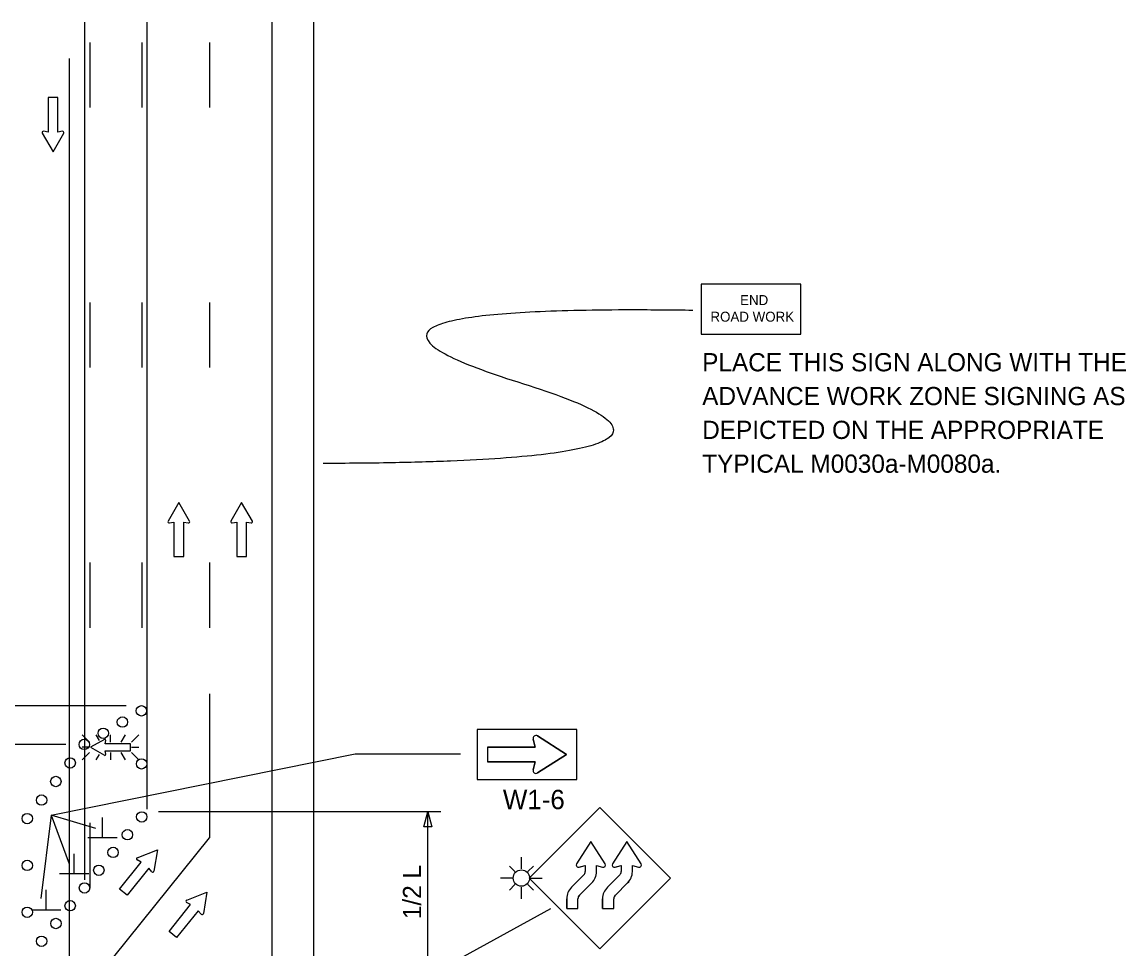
# Model space of a CAD drawing. Extents: x 16525 to 18479, y 5726 to 6926.
# Drawn here: x 16973 to 17397.4, y 6569.7 to 6926.1 of the extents above; entities that cross this region are included whole.
import ezdxf

# ---------------------------------------------------------------- set-up
doc = ezdxf.new("R2010")
doc.units = 0
for name, color, linetype in [('ALI_LEGAL_EX', 7, 'Continuous'), ('MT_SCRATCH_LEVEL_E', 7, 'Continuous'), ('PAVT_EDGE_EX', 7, 'Continuous'), ('TRAFFIC_SIGNS_PR', 7, 'Continuous'), ('TYPICAL_TEXT_DIMEN_PR', 7, 'Continuous')]:
    doc.layers.add(name, color=color, linetype=linetype)

msp = doc.modelspace()

# ---------------------------------------------------------------- linework, layer by layer
at = {"layer": 'ALI_LEGAL_EX'}
for points in [[(16999, 6918.24), (16999, 6893.24)], [(17019, 6918.24), (17019, 6893.24)], [(17045, 6918.24), (17045, 6893.24)], [(16999, 6818.24), (16999, 6793.24)], [(16999, 6818.24), (16999, 6793.24)], [(17019, 6818.24), (17019, 6793.24)], [(17019, 6818.24), (17019, 6793.24)], [(17045, 6818.24), (17045, 6793.24)], [(17045, 6818.24), (17045, 6793.24)], [(16999, 6718.24), (16999, 6693.24)], [(16999, 6718.24), (16999, 6693.24)], [(17019, 6718.24), (17019, 6693.24)], [(17019, 6718.24), (17019, 6693.24)], [(17045, 6718.24), (17045, 6693.24)], [(17045, 6718.24), (17045, 6693.24)], [(16999, 6618.24), (16999, 6593.24)], [(16999, 6618.24), (16999, 6593.24)]]:
    msp.add_lwpolyline(points, dxfattribs=at)
at = {"layer": 'MT_SCRATCH_LEVEL_E'}
for p, q in [((16986.74, 6897.03), (16983, 6897.03)), ((16983, 6897.03), (16983, 6883.77)), ((16986.74, 6897.03), (16983, 6897.03)), ((16983, 6897.03), (16983, 6883.77)), ((16986.74, 6883.77), (16986.74, 6897.03)), ((16986.74, 6883.77), (16986.74, 6897.03)), ((16980.74, 6883.4), (16984.89, 6876.16)), ((16980.74, 6883.4), (16984.89, 6876.16)), ((16983, 6883.77), (16981.22, 6884.09)), ((16983, 6883.77), (16981.22, 6884.09)), ((16984.89, 6876.16), (16989, 6883.4)), ((16984.89, 6876.16), (16989, 6883.4)), ((16988.52, 6884.09), (16986.74, 6883.77)), ((16988.52, 6884.09), (16986.74, 6883.77)), ((17033.24, 6741.41), (17029.13, 6734.17)), ((17033.24, 6741.41), (17029.13, 6734.17)), ((17037.39, 6734.17), (17033.24, 6741.41)), ((17037.39, 6734.17), (17033.24, 6741.41)), ((17057.41, 6741.41), (17053.3, 6734.17)), ((17057.41, 6741.41), (17053.3, 6734.17)), ((17061.56, 6734.17), (17057.41, 6741.41)), ((17061.56, 6734.17), (17057.41, 6741.41)), ((17029.61, 6733.49), (17031.39, 6733.8)), ((17029.61, 6733.49), (17031.39, 6733.8)), ((17031.39, 6733.8), (17031.39, 6720.55)), ((17031.39, 6733.8), (17031.39, 6720.55)), ((17035.13, 6720.55), (17035.13, 6733.8)), ((17035.13, 6733.8), (17036.91, 6733.49)), ((17035.13, 6720.55), (17035.13, 6733.8)), ((17035.13, 6733.8), (17036.91, 6733.49)), ((17053.78, 6733.49), (17055.56, 6733.8)), ((17053.78, 6733.49), (17055.56, 6733.8)), ((17055.56, 6733.8), (17055.56, 6720.55)), ((17055.56, 6733.8), (17055.56, 6720.55)), ((17059.3, 6720.55), (17059.3, 6733.8)), ((17059.3, 6733.8), (17061.08, 6733.49)), ((17059.3, 6720.55), (17059.3, 6733.8)), ((17059.3, 6733.8), (17061.08, 6733.49)), ((17031.39, 6720.55), (17035.13, 6720.55)), ((17031.39, 6720.55), (17035.13, 6720.55)), ((17055.56, 6720.55), (17059.3, 6720.55)), ((17055.56, 6720.55), (17059.3, 6720.55)), ((17017.25, 6604.77), (17025.02, 6607.81)), ((17017.25, 6604.77), (17025.02, 6607.81)), ((17025.02, 6607.81), (17023.68, 6599.59)), ((17025.02, 6607.81), (17023.68, 6599.59)), ((17010.46, 6592.74), (17018.78, 6603.07)), ((17010.46, 6592.74), (17018.78, 6603.07)), ((17021.69, 6600.72), (17013.38, 6590.4)), ((17021.69, 6600.72), (17013.38, 6590.4)), ((17018.78, 6603.07), (17017.19, 6603.94)), ((17018.78, 6603.07), (17017.19, 6603.94)), ((17022.88, 6599.36), (17021.69, 6600.72)), ((17022.88, 6599.36), (17021.69, 6600.72)), ((17013.38, 6590.4), (17010.46, 6592.74)), ((17013.38, 6590.4), (17010.46, 6592.74)), ((17036.29, 6588.46), (17044.06, 6591.49)), ((17036.29, 6588.46), (17044.06, 6591.49)), ((17044.06, 6591.49), (17042.72, 6583.28)), ((17044.06, 6591.49), (17042.72, 6583.28)), ((17037.81, 6586.75), (17036.23, 6587.62)), ((17037.81, 6586.75), (17036.23, 6587.62)), ((17029.5, 6576.43), (17037.81, 6586.75)), ((17029.5, 6576.43), (17037.81, 6586.75)), ((17040.73, 6584.41), (17032.41, 6574.08)), ((17040.73, 6584.41), (17032.41, 6574.08)), ((17041.92, 6583.05), (17040.73, 6584.41)), ((17041.92, 6583.05), (17040.73, 6584.41)), ((17032.41, 6574.08), (17029.5, 6576.43)), ((17032.41, 6574.08), (17029.5, 6576.43))]:
    msp.add_line(p, q, dxfattribs=at)
for centre, start, end in [((16981.15, 6883.63), 80.0362, 209.7731), ((16981.15, 6883.63), 80.0362, 209.7731), ((16988.59, 6883.63), 330.4248, 99.9638), ((16988.59, 6883.63), 330.4248, 99.9638), ((17029.54, 6733.95), 150.4248, 279.9638), ((17029.54, 6733.95), 150.4248, 279.9638), ((17036.98, 6733.95), 260.0362, 29.7731), ((17036.98, 6733.95), 260.0362, 29.7731), ((17053.71, 6733.95), 150.4248, 279.9638), ((17053.71, 6733.95), 150.4248, 279.9638), ((17061.15, 6733.95), 260.0362, 29.7731), ((17061.15, 6733.95), 260.0362, 29.7731), ((17017.43, 6604.34), 111.3861, 241.123), ((17017.43, 6604.34), 111.3861, 241.123), ((17023.22, 6599.67), 221.1954, 350.7344), ((17023.22, 6599.67), 221.1954, 350.7344), ((17036.47, 6588.02), 111.3861, 241.123), ((17036.47, 6588.02), 111.3861, 241.123), ((17042.26, 6583.36), 221.1954, 350.7344), ((17042.26, 6583.36), 221.1954, 350.7344)]:
    msp.add_arc(centre, 0.463, start, end, dxfattribs=at)
at = {"layer": 'PAVT_EDGE_EX'}
for p, q in [((16997, 6926.09), (16997, 6596.31)), ((17021, 6926.09), (17021, 6623.4)), ((17069, 6926.09), (17069, 6062.8)), ((17085, 6926.09), (17085, 6062.8)), ((16991.07, 6912.1), (16991.07, 6082.91)), ((16997, 6871.73), (16997, 6598.71)), ((17021, 6871.73), (17021, 6629.58)), ((17045, 6667.86), (17045, 6612.39)), ((16997, 6552.78), (17045, 6612.39))]:
    msp.add_line(p, q, dxfattribs=at)
at = {"layer": 'TRAFFIC_SIGNS_PR'}
for p, q in [((16996.08, 6652.08), (16998.9, 6649.26)), ((17002.8, 6649.89), (17001.54, 6652.08)), ((17006.99, 6649.26), (17006.99, 6652.08)), ((17011.12, 6649.26), (17012.75, 6652.08)), ((17015.07, 6649.26), (17017.89, 6652.08)), ((17171.18, 6651.59), (17182.34, 6644.49)), ((16998.9, 6647.23), (16996.08, 6647.23)), ((17015.07, 6647.23), (17017.89, 6647.23)), ((17151.94, 6647.29), (17170.34, 6647.29)), ((17151.94, 6647.29), (17151.94, 6641.69)), ((17170.34, 6647.29), (17169.5, 6650.35)), ((16996.08, 6642.38), (16998.9, 6645.19)), ((17001.52, 6642.37), (17002.72, 6644.47)), ((17006.99, 6645.19), (17006.99, 6642.37)), ((17012.77, 6642.37), (17011.15, 6645.19)), ((17015.07, 6645.19), (17017.89, 6642.37)), ((17182.34, 6644.49), (17171.18, 6637.39)), ((17170.34, 6641.69), (17151.94, 6641.69)), ((17169.5, 6638.63), (17170.34, 6641.69)), ((17195.14, 6624.05), (17167.99, 6596.9)), ((17222.29, 6596.9), (17195.14, 6624.05)), ((17164.98, 6600.52), (17164.98, 6605.03)), ((17162.46, 6599.48), (17160.36, 6601.59)), ((17167.49, 6599.48), (17169.6, 6601.59)), ((17161.82, 6596.97), (17156.99, 6596.97)), ((17167.99, 6596.9), (17195.14, 6569.75)), ((17168.13, 6596.97), (17173.01, 6596.97)), ((17184.27, 6593.44), (17188.99, 6598.15)), ((17188.99, 6598.15), (17184.27, 6593.44)), ((17195.14, 6569.75), (17222.29, 6596.9)), ((17198.07, 6593.44), (17202.78, 6598.15)), ((17202.78, 6598.15), (17198.07, 6593.44)), ((17162.46, 6594.46), (17160.36, 6592.35)), ((17164.98, 6589), (17164.98, 6593.41)), ((17167.49, 6594.46), (17169.6, 6592.35)), ((17187.32, 6590.38), (17192.04, 6595.1)), ((17187.32, 6590.38), (17192.04, 6595.1)), ((17201.12, 6590.38), (17205.83, 6595.1)), ((17201.12, 6590.38), (17205.83, 6595.1)), ((17182.4, 6585.32), (17182.4, 6589.02)), ((17186.72, 6585.32), (17186.72, 6589.02)), ((17196.2, 6585.32), (17196.2, 6589.02)), ((17200.52, 6585.32), (17200.52, 6589.02)), ((17182.4, 6585.32), (17186.72, 6585.32)), ((17196.2, 6585.32), (17200.52, 6585.32))]:
    msp.add_line(p, q, dxfattribs=at)
for points in [[(17234.07, 6806.15), (17272.47, 6806.15), (17272.47, 6825.35), (17234.07, 6825.35)], [(17147.94, 6634.89), (17186.34, 6634.89), (17186.34, 6654.09), (17147.94, 6654.09)]]:
    msp.add_lwpolyline(points, close=True, dxfattribs=at)
for points in [[(17171.18, 6637.39), (17182.34, 6644.49), (17171.18, 6651.59)], [(17004.66, 6650.24), (16999.35, 6647.23), (17004.66, 6644.19)], [(17005.16, 6644.54), (17004.93, 6645.84), (17014.65, 6645.84), (17014.65, 6648.58), (17004.93, 6648.58), (17005.16, 6649.89)], [(17169.5, 6650.35), (17170.34, 6647.29), (17151.94, 6647.29), (17151.94, 6641.69), (17170.34, 6641.69), (17169.5, 6638.63)], [(17197.19, 6602.43), (17191.71, 6611.04), (17186.23, 6602.42)], [(17197.19, 6602.42), (17191.71, 6611.04), (17186.23, 6602.42)], [(17210.99, 6602.43), (17205.5, 6611.04), (17200.02, 6602.42)], [(17210.99, 6602.42), (17205.5, 6611.04), (17200.02, 6602.42)], [(17187.19, 6601.13), (17189.55, 6601.78), (17189.55, 6599.48)], [(17187.19, 6601.13), (17188.02, 6601.36), (17189.55, 6601.78), (17189.55, 6599.48)], [(17193.86, 6599.41), (17193.87, 6601.78), (17196.23, 6601.13)], [(17193.86, 6599.41), (17193.87, 6601.78), (17196.23, 6601.13)], [(17200.98, 6601.13), (17203.34, 6601.78), (17203.34, 6599.48)], [(17200.98, 6601.13), (17201.82, 6601.36), (17203.34, 6601.78), (17203.34, 6599.48)], [(17207.66, 6599.41), (17207.66, 6601.78), (17210.03, 6601.13)], [(17207.66, 6599.41), (17207.66, 6601.78), (17210.03, 6601.13)], [(17182.4, 6589.02), (17182.4, 6585.32), (17186.72, 6585.32), (17186.72, 6589.02)], [(17196.2, 6589.02), (17196.2, 6585.32), (17200.52, 6585.32), (17200.52, 6589.02)]]:
    msp.add_lwpolyline(points, dxfattribs=at)
for centre, radius in [((17018.88, 6661.27), 2), ((17011.56, 6656.96), 2), ((17004.23, 6652.65), 2), ((16996.9, 6648.34), 2), ((16991.48, 6641.21), 2), ((17018.94, 6640.87), 2), ((16985.99, 6634.08), 2), ((16980.49, 6626.95), 2), ((16975, 6619.82), 2), ((17019, 6620.47), 2), ((17013.5, 6613.64), 2), ((17008, 6606.81), 2), ((16975, 6601.82), 2), ((17002.5, 6599.98), 2), ((17164.98, 6596.97), 3.15), ((16997, 6593.15), 2), ((16991.5, 6586.32), 2), ((16975, 6583.82), 2), ((16986, 6579.49), 2), ((16980.5, 6572.66), 2)]:
    msp.add_circle(centre, radius, dxfattribs=at)
for centre, radius, start, end in [((17170.58, 6650.65), 1.12, 57.5304, 195.3269), ((17170.58, 6650.65), 1.12, 57.5304, 195.3269), ((17004.82, 6649.94), 0.341, 350.7308, 118.8916), ((17004.82, 6644.49), 0.341, 241.4833, 9.9593), ((17170.58, 6638.33), 1.12, 164.6731, 302.4696), ((17170.58, 6638.33), 1.12, 164.6731, 302.4696), ((17186.96, 6601.96), 0.866, 147.5288, 285.3852), ((17186.96, 6601.96), 0.864, 147.5204, 285.3986), ((17196.46, 6601.96), 0.866, 254.6828, 32.2708), ((17196.46, 6601.96), 0.866, 254.6799, 32.2804), ((17193.38, 6590.71), 10.8, 74.68, 74.6808), ((17206.3, 6608.22), 10.8, 212.4569, 212.4665), ((17200.75, 6601.96), 0.866, 147.5288, 285.3852), ((17200.75, 6601.96), 0.864, 147.5204, 285.3986), ((17210.26, 6601.96), 0.866, 254.6828, 32.2708), ((17210.25, 6601.96), 0.866, 254.6799, 32.2804), ((17207.17, 6590.71), 10.8, 74.68, 74.6808), ((17220.1, 6608.22), 10.8, 212.4569, 212.4665), ((17187.69, 6599.48), 1.85, 314.2125, 0), ((17187.69, 6599.48), 1.85, 314.2123, 0.1238), ((17187.69, 6599.48), 6.17, 314.2125, 359.3819), ((17187.69, 6599.48), 6.17, 314.7687, 359.3755), ((17201.49, 6599.48), 1.85, 314.2125, 0), ((17201.49, 6599.48), 1.85, 314.2123, 0.1238), ((17201.49, 6599.48), 6.17, 314.2125, 359.3819), ((17201.49, 6599.48), 6.17, 314.7687, 359.3755), ((17188.57, 6589.02), 6.17, 134.2125, 180), ((17188.57, 6589.02), 6.17, 134.2125, 180), ((17188.57, 6589.02), 6.17, 134.2117, 180), ((17202.37, 6589.02), 6.17, 134.2125, 180), ((17202.37, 6589.02), 6.17, 134.2125, 180), ((17202.37, 6589.02), 6.17, 134.2117, 180), ((17188.57, 6589.02), 1.85, 132.372, 180), ((17188.57, 6589.02), 1.85, 134.2125, 180), ((17202.37, 6589.02), 1.85, 132.372, 180), ((17202.37, 6589.02), 1.85, 134.2125, 180)]:
    msp.add_arc(centre, radius, start, end, dxfattribs=at)
msp.add_open_spline([(17230.88, 6815.23), (17067.17, 6817.61), (17263.08, 6756.87), (17088.82, 6756.35)], degree=2, dxfattribs=at)
at = {"layer": 'TYPICAL_TEXT_DIMEN_PR'}
for p, q in [((16883.9, 6663.27), (17013.03, 6663.27)), ((16989.81, 6648.35), (16858.32, 6648.35)), ((16984.19, 6621.12), (17101.05, 6644.73)), ((17101.05, 6644.73), (17141.51, 6644.73)), ((16984.19, 6621.12), (16980.18, 6589.12)), ((17001.33, 6616), (16984.19, 6621.12)), ((16984.19, 6621.12), (16991.12, 6602.47)), ((17134, 6622.47), (17025.42, 6622.47)), ((17127.43, 6616.61), (17129, 6622.47)), ((17129, 6563.82), (17129, 6622.47)), ((17129, 6622.47), (17130.57, 6616.61)), ((17003.9, 6612.46), (17003.9, 6620.25)), ((17129, 6616.61), (17127.43, 6616.61)), ((17130.57, 6616.61), (17129, 6616.61)), ((17009.53, 6612.46), (16998.28, 6612.46)), ((16993.08, 6598.54), (16993.08, 6606.32)), ((16998.7, 6598.54), (16987.45, 6598.54)), ((16982.25, 6584.61), (16982.25, 6592.4)), ((16987.87, 6584.61), (16976.62, 6584.61)), ((17176.23, 6585.1), (17140.02, 6565.3))]:
    msp.add_line(p, q, dxfattribs=at)

# ---------------------------------------------------------------- texts
at = {"layer": 'TRAFFIC_SIGNS_PR'}
for s, height, p in [('END', 3.831, (17249.08, 6817.28)), ('ROAD WORK', 3.831, (17237.68, 6810.89)), ('PLACE THIS SIGN ALONG WITH THE', 7, (17234.51, 6791.8)), ('ADVANCE WORK ZONE SIGNING AS', 7, (17234.51, 6778.8)), ('DEPICTED ON THE APPROPRIATE', 7, (17234.51, 6765.8)), ('TYPICAL M0030a-M0080a.', 7, (17234.51, 6752.8)), ('W1-6', 7.44, (17157.88, 6623.45))]:
    msp.add_text(s, height=height, dxfattribs=at).set_placement(p)
at = {"layer": 'TYPICAL_TEXT_DIMEN_PR'}
msp.add_text('1/2 L', height=7, rotation=90, dxfattribs=at).set_placement((17126.44, 6581.18))

doc.saveas('drawing.dxf')
